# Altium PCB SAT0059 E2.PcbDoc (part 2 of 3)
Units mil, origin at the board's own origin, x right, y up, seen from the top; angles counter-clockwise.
Board outline 3960.27 x 3100.03 mil, 6 copper layers (Top Layer, GND, Power, Inner Routing, GND 2, Bottom Layer), stack 59.2 mil thick; 276 components, 209 nets, 812 pads, 621 vias.
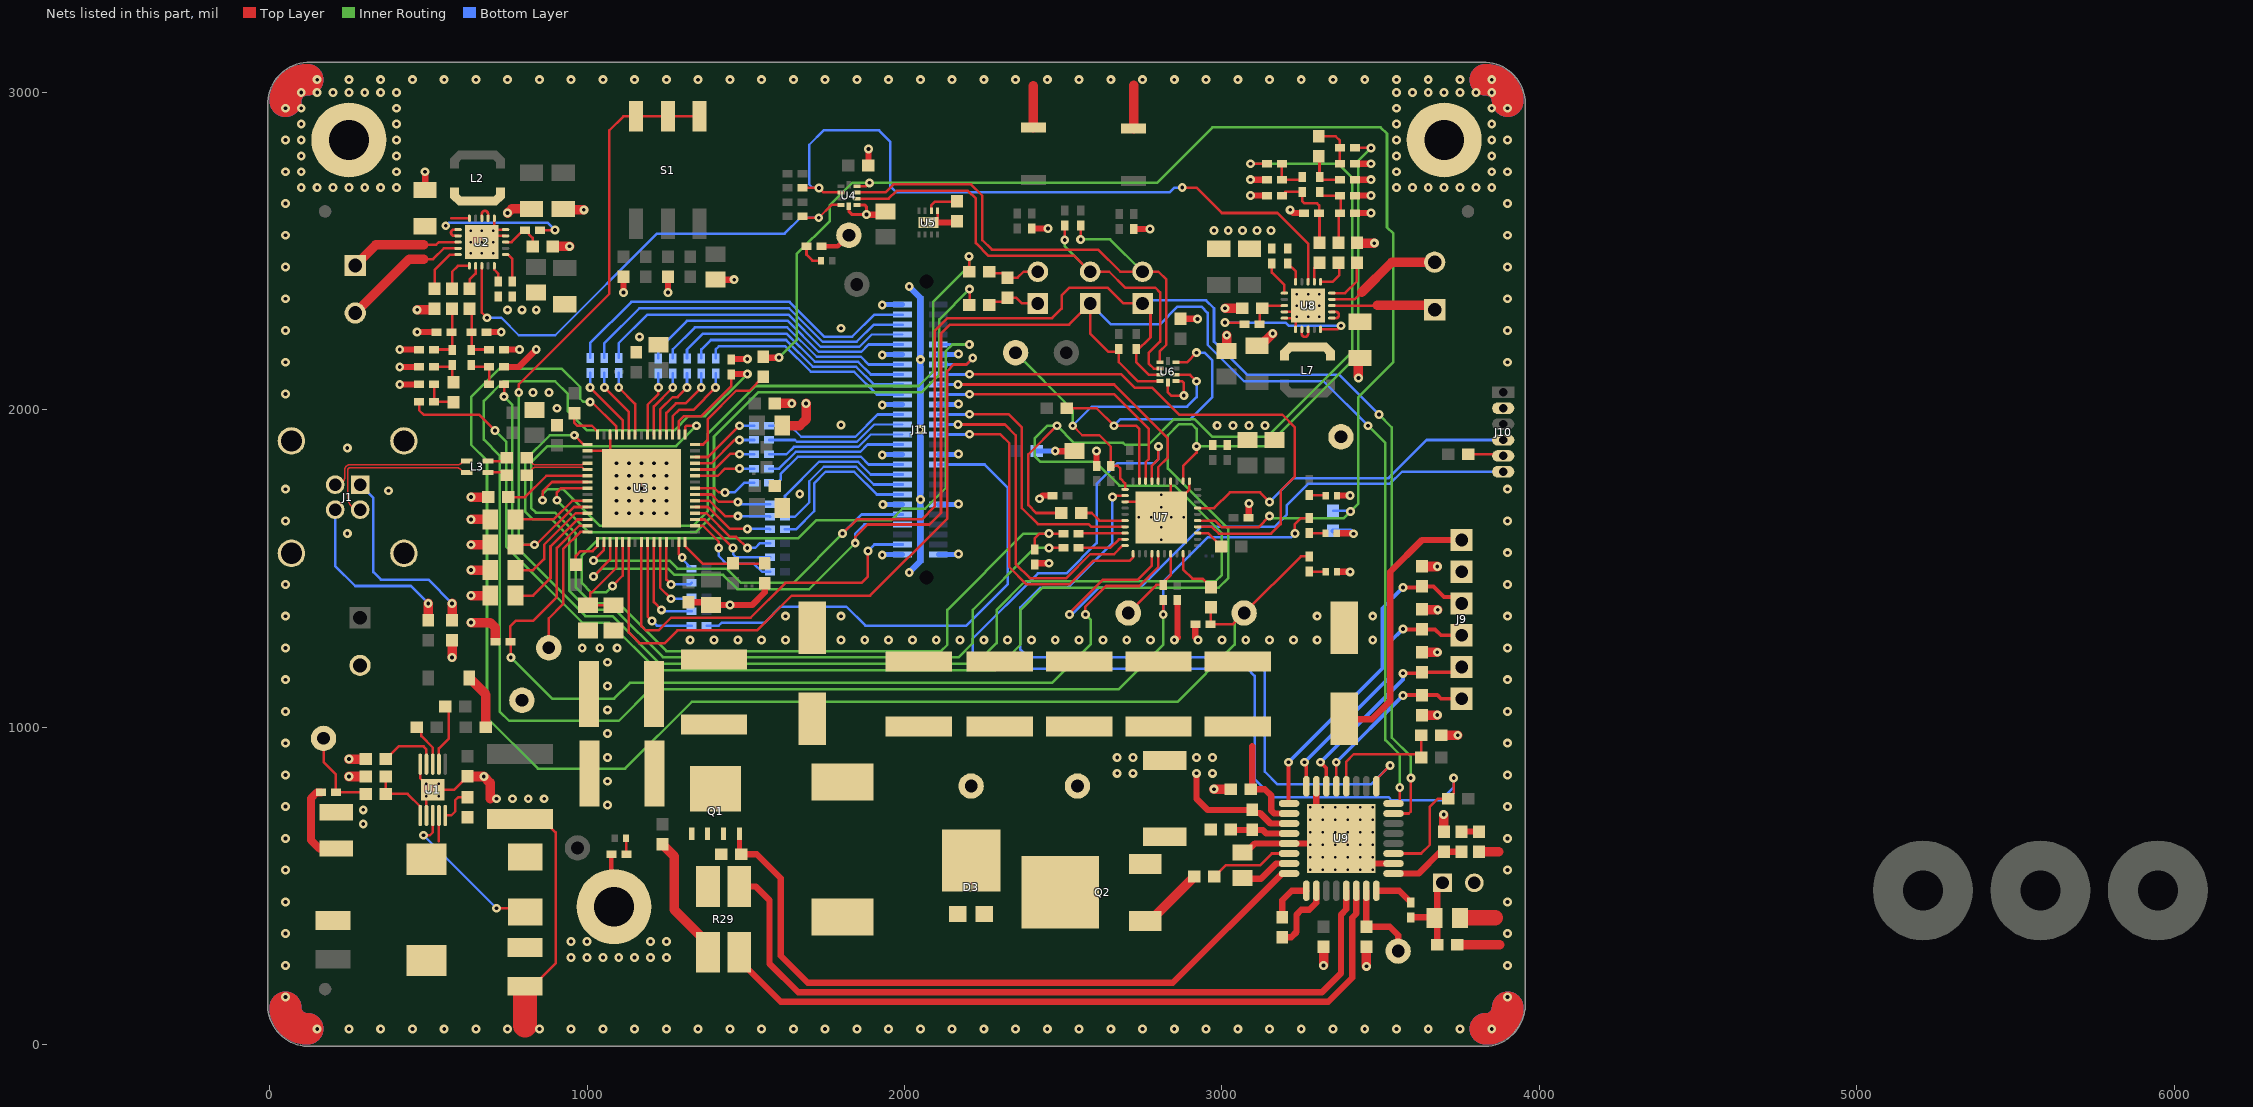
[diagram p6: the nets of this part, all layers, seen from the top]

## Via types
v1: diameter 28, hole 12, Top Layer to Bottom Layer, 528 vias
v2: diameter 19.68, hole 7.87, Top Layer to Bottom Layer, 44 vias
v3: diameter 23.62, hole 11.81, Top Layer to Bottom Layer, 25 vias
v4: diameter 19.68, hole 7.87, Top Layer to Bottom Layer, tented both sides, 20 vias
v5: diameter 18.75, hole 7.87, Top Layer to Bottom Layer, 4 vias

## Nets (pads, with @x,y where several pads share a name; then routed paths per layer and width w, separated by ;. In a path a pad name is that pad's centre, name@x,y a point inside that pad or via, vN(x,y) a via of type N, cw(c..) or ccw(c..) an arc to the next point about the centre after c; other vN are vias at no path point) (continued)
BLU7: J11.34 R99.2 | length 1605.9
  Bottom Layer w8: R99.2@1376.81,1320 1415,1320 1425,1330 1560,1330 1610,1380 1816.56,1380 1876.56,1320 2195,1320 2325.12,1450.12 2325.12,1754.88 2252.24,1827.76 J11.34@2106.1,1827.76
CMLOUTN: C48.1 U3.53 | length 2081
  Top Layer w8: v1(905,1715) 905,1740 918.01,1753.01 U3.53@1002.06,1753.01 ; C48.1@2203.5,2330 2205,2331.5 v1(2205,2380)
  Inner Routing w8: v1(905,1715) 1005,1615 1343.28,1615 1400,1671.72 1400,1916.02 1538.98,2055 2053.28,2055 2110,2111.72 2110,2285 v1(2205,2380)
CMLOUTP: C47.1 U3.52 | length 2289.2
  Top Layer w8: v1(860,1715) 860,1742.99 889.7,1772.7 U3.52@1002.06,1772.7 ; C47.1@2203.5,2435 v1(2203.5,2483.5)
  Inner Routing w8: v1(860,1715) 860,1735 875,1750 925,1750 1040,1635 1335,1635 1380,1680 1380,1924.31 1530.69,2075 2045,2075 2090,2120 2090,2339.98 2203.5,2453.49 v1(2203.5,2483.5)
DEN: J11.14 U3.6 | length 2143.9
  Top Layer w8: U3.6@1131.98,1583.72 1131.98,1298.02 1165,1265 1245,1265 1285,1305 1535,1305 1645,1415 1892,1415 2135,1658 2135,2122.72 2155,2142.72 2194.76,2142.72 v1(2215,2162.96)
  Bottom Layer w8: J11.14@2106.1,2142.72 2194.76,2142.72 v1(2215,2162.96)
DRV_FILTER_EN: R7.2 R71.2 U7.2 | length 5462
  Top Layer w8: R7.2@471.38,2025 471.38,1998.62 485,1985 660,1985 v1(710,1935) ; U7.2@2877.9,1775.17 2877.9,1822.9 2920,1865 v1(2920,1885) ; R71.2@3418.62,2825 v1(3470,2825)
  Inner Routing w8: v1(710,1935) 745,1900 745,1570 985,1330 1070,1330 1220,1180 2285,1180 2365,1260 2365,1370 2435,1440 2990,1440 3020,1470 3020,1625 2830,1815 2830,1920 2865,1955 2905,1955 2920,1940 v1(2920,1885) 3140.5,1885 3430,2174.5 3430,2785 v1(3470,2825)
DRV_PWM: R18.1 R44.1 R63.1 | length 6506.4
  Top Layer w8: v1(738.62,2041.38) R18.1@738.62,2080 ; v1(2480,1950) 2390,1860 2390,1700 2415,1675 R44.1@2493.5,1675 ; v1(3090,2775) R63.1@3141.38,2775
  Inner Routing w8: v1(738.62,2041.38) 765,2015 765,1580 995,1350 1080,1350 1230,1200 2225,1200 2290,1265 2290,1370 2380,1460 2980,1460 3000,1480 3000,1611.16 2850,1761.16 2677.07,1761.16 2602.23,1836 2429,1836 2410,1855 2410,1910 2450,1950 v1(2480,1950) 2534,1896 2689,1896 2695,1890 2768.23,1890 2849.23,1971 2911.63,1971 2912.63,1970 2915,1970 2970,1915 3142.27,1915 3410,2182.73 3410,2731.65 3366.65,2775 v1(3090,2775)
FB: C49.1 C51.1 C54.1 C57.1 C62.1 C74.1 D3.3 J9.1 U9.26 VBOOST.1 | length 1123.3
  Top Layer w20: 3095,940 3095,808.5 C62.1@3091.5,805 3135,805 3155,785 3155,738 3164.57,728.43 U9.26@3211.57,728.43 ; C74.1@3420,1025 3472.06,1025 3530,1082.94 3530,1490 3630,1590 J9.1@3755,1590
GND: C1.2 C2.2 C3.2 C4.2 C5.2 C8.2 C10.2 C11.2 C12.2 C14.2 C15.2 C16.2 C17.2 C18.2 C19.2 C22.2 C23.2 C24.2 C25.2 C26.2 C27.2 C28.2 C29.2 C30.2 C31.2 C32.2 C33.2 C34.2 C35.2 C36.2 C37.2 C38.2 C39.2 C40.2 C41.2 C42.2 C43.2 C44.2 C45.2 C46.2 C49.2 C50.2 C51.2 C52.2 C53.2 C54.2 C55.2 C56.2 C57.2 C58.2 C59.2 C60.2 C61.2 C62.2 C63.2 C64.2 C65.2 C66.2 C67.1 C68.2 C69.2 C70.2 C71.2 C73.2 C74.2 C76.1 C78.2 C79.2 C80.2 C81.2 C82.2 C83.2 C84.2 C85.2 C86.2 D4.2 D5.2 D6.2 J1.5 J1.6 J1.7 J1.8 J3.2 J8.2 J9.2 J10.2 J11.1 J11.11 J11.12 J11.21 J11.22 J11.31 J11.32 J11.41 J11.42 J11.51 J11.52 J11.53 J11.54 J11.55 J11.56 pad.0 R3.1 R6.1 R9.1 R10.1 R12.1 R16.1 R19.1 R20.1 R22.1 R25.1 R27.1 R30.1 R33.1 R35.1 R42.1 R43.1 R52.1 R54.1 R56.1 R60.1 R61.1 R65.1 R72.1 R73.1 R74.1 R75.1 R77.2 R79.2 R107.1 R108.1 R111.2 R113.2 RESET.2 RT1.1 TP11.1 TP12.1 TP13.1 U1.5 U1.7 U1.11 U2.4 U2.5 U2.6 U2.21 U3.43 U3.47 U3.61 U4.5 U4.6 U5.5 U5.9 U6.5 U6.6 U7.1 U7.4 U7.13 U7.41 U8.4 U8.5 U8.6 U8.21 U9.10 U9.23 U9.27 U9.29 U9.33 USER.2 | length 10442
  Top Layer w8: U1.5@474.63,883.71 474.63,839.37 511,803 U1.11@514,803 581.48,803 624,845.52 C8.2@624,846.5 ; U1.7@494.32,722.29 v5(494.31,783.32) ; U2.21@688.18,2548.04 U2.4@743.3,2548.04 ; U2.6@707.87,2603.16 707.87,2567.73 U2.5@743.3,2567.73 ; R20.1@805,183.98 828.98,183.98 901,256 901,669 C18.2@859.36,710.64 ; U3.47@1002.06,1871.12 U3.61@1053.24,1871.12 ; U3.61@1072.93,1851.44 U3.43@1072.93,1922.3 ; U5.9@2104.53,2595.47 U5.5@2104.53,2627.4 ; U7.13@2694.83,1710.21 U7.41@2759.79,1710.21 ; U7.41@2809,1661 U7.41@2838.53,1690.53 ; U6.5@2830,2086.14 2830,2055 2840,2045 v1(2880,2045) 2880,2085 2874.53,2090.47 U6.6@2855.2,2090.47 ; U7.4@2838.53,1775.17 U7.41@2838.53,1690.53 ; U7.1@2897.58,1775.17 2897.58,1749.58 U7.41@2838.53,1690.53 ; U8.5@3196.56,2288.9 3231.99,2288.9 U8.6@3231.99,2253.47 ; U8.4@3196.56,2308.59 U8.21@3251.68,2308.59
  Top Layer w10: U4.5@1825,2641.14 1825,2625 1835,2615 v1(1880,2615) 1880,2640 1874.53,2645.47 U4.6@1850.2,2645.47
  Top Layer w15: pad.0@1076.38,443.62 R107.1@1076.38,600 ; R108.1@1738.62,2515 1790,2515 TP13.1@1825,2550
  Top Layer w20: v1(410,2080) R6.1@471.38,2080 ; v1(410,2135) C5.2@471.38,2135 ; v1(410,2190) C4.2@471.38,2190 ; v1(465,2245) R10.1@526.38,2245 ; C3.2@490,2692.09 v1(490,2750) ; R16.1@683.62,2245 v1(730,2245) ; C17.2@740.59,2135 785,2135 v1(840,2190) ; C16.2@740.59,2190 v1(786.97,2190) ; v1(1115,2370) R25.1@1115,2415.57 ; v1(1255,2370) R27.1@1255,2415.57 ; C36.2@1320,1393.5 1381.5,1393.5 C37.2@1390,1385 v1(1450,1385) 1520,1385 1560,1425 R35.1@1560,1450.55 ; R30.1@1417.93,2410 v1(1463.5,2410) ; R33.1@1455,2158.62 1456.38,2160 v1(1505,2160) ; v1(1880,2615) 1930,2615 C44.2@1940,2625 ; C43.2@1886.5,2770 v1(1886.5,2821.5) ; U5.9@2075,2590 v2(2090.75,2590) ; U5.9@2104.53,2590 2161.5,2590 C46.2@2165,2593.5 ; C50.2@2401,2571.02 v1(2452.38,2571.02) ; R42.1@2410,1513.19 2413.62,1516.81 v1(2455,1516.81) ; v1(2425,1720) 2435,1730 R43.1@2466.38,1730 ; v1(2475,1870) C52.2@2535,1870 ; C53.2@2605,1823.62 v1(2605,1870) ; C55.2@2722,2569.38 v1(2773.38,2569.38) ; R54.1@2860,1401.38 2860,1285 2861.38,1283.62 ; C56.2@2870,2286.5 v1(2923.5,2286.5) ; R56.1@2916.38,1325 2916.38,1283.62 v1(2925,1275) ; v1(2920,855) 2920,775 2955.39,739.61 C67.1@3095.63,739.61 ; C63.2@3065,615 3085,615 3103.94,633.94 U9.29@3211.57,633.94 U9.33@3360.2,633.94 ; R60.1@3083.62,1660 3085,1661.38 v1(3085,1705) ; v1(3090,2675) C69.2@3141.38,2675 ; v1(3090,2725) C68.2@3141.38,2725 ; C67.1@3105.24,730 3120,730 3153.07,696.93 U9.27@3211.57,696.93 ; v1(3215,2630) 3225,2620 R65.1@3258.74,2620 ; U9.33@3297.2,728.43 U9.23@3297.2,814.06 ; D4.2@3361.48,1611.24 3412.52,1611.24 v1(3414.02,1609.74) ; D6.2@3363.02,1490 v1@3403.76,1490 ; D5.2@3363.02,1730 3403.76,1730 v1(3404.02,1729.74) ; R73.1@3418.62,2620 v1(3470,2620) ; C79.2@3418.62,2675 v1(3470,2675) ; C78.2@3418.62,2725 v1(3470,2725) ; R72.1@3418.62,2775 v1(3470,2775) ; U9.33@3454.69,570.94 U9.10@3540.31,570.94
  Top Layer w30: v1(250,845) R3.1@303.5,845 ; v1(250,900) C2.2@303.5,900 ; v1(465,2315) 516.5,2315 R9.1@520,2318.5 ; v1(575,1220) R12.1@575,1273.5 ; C8.2@624,846.5 625.5,845 v1(675,845) 695,825 695,775 ; v1(635,1330) 695,1330 711.38,1313.62 R19.1@711.38,1280 ; v1(635,1415) C15.2@695,1415 ; v1(635,1495) C12.2@695,1495 ; v1(635,1575) C14.2@695,1575 ; v1(635,1655) C11.2@695,1655 ; v1(635,1725) C10.2@685.57,1725 ; v1(750,2620) 762.91,2632.91 C23.2@825,2632.91 ; R22.1@891.5,2515 v1(945,2515) ; C26.2@925,2632.91 927.91,2630 v1(990,2630) ; C38.2@1591.5,2020 v1(1645,2020) ; C40.2@1615,1950 1670,1950 1690,1970 v1(1690,2020) ; RESET.2@2406,2888.69 2406,3021 ; USER.2@2722,2885.68 2722,3022 ; v1(2975,805) C62.2@3028.5,805 ; v1(3010,2320) R61.1@3060.57,2320 ; C60.2@3015,2180 v1(3015,2235) ; C66.2@3110,2192.09 C66.2@3122.09,2192.09 ; C66.2@3122.09,2202.09 v1(3160,2240) ; v1(3320,250) C76.1@3320,308.5 ; R74.1@3425,2526.5 3426.5,2525 v1(3480,2525) ; v1@3430,2105 C80.2@3430,2162.91 ; v1(3455,247.07) R75.1@3455,305.57 ; C84.2@3628.5,1040 C84.2@3630,1038.5 v1(3678.5,1038.5) ; C83.2@3628.5,1237.99 C83.2@3630,1236.5 v1(3678.5,1236.5) ; C81.2@3628.5,1507.99 C81.2@3630,1506.5 v1(3678.5,1506.5) ; C82.2@3630,1371.5 3631.5,1370 v1(3680,1370) ; R77.2@3692.93,976.5 3694.43,975 v1(3742.93,975) ; v1(3698.5,725) 3698.5,676.5 C85.2@3700,675 ; R79.2@3741.5,315 3875,315 ; C86.2@3810,608.5 3871.5,608.5
  Top Layer w50: RT1.1@3750,400 3860,400
  Top Layer w75: 805,60 R20.1@805,165
  Top Layer w100: 50,118 ccw(c118,118.01) 120.22,50.05 ; 50,2972 cw(c118,2971.99) 120.22,3039.95 ; 3829.78,3039.95 cw(c3832,2971.99) 3900,2972 ; 3830,50 ccw(c3832.22,117.96) 3900.22,117.95
  Bottom Layer w15: v1@1931.22,1544.3 J11.51@1993.9,1544.3 ; v1@1931.22,1859.26 J11.31@1993.9,1859.26 ; v1@1931.22,2016.74 J11.21@1993.9,2016.74 ; v1@1931.22,2174.22 J11.11@1993.9,2174.22 ; v1@1931.22,2331.7 J11.1@1993.9,2331.7 ; v1(1931.78,1701.78) J11.41@1993.9,1701.78 ; J11.52@2106.1,1544.3 v1@2168.78,1544.3 ; J11.42@2106.1,1701.78 v1@2168.78,1701.78 ; J11.32@2106.1,1859.26 v1@2168.78,1859.26 ; J11.22@2106.1,2016.74 v1@2168.78,2016.74 ; J11.12@2106.1,2174.22 v1@2168.78,2174.22 ; R111.2@2416.5,1870 v1(2475,1870) ; R113.2@3350,1618.5 3405.26,1618.5 v1(3414.02,1609.74)
  Bottom Layer w20: v1(2015,1488) 2050,1523 J11.56@2050,1607.29 v1(2050,1718) J11.55@2050,1827.76 J11.54@2050,2048.24 v1(2050,2158) J11.53@2050,2268.71 2050,2353 v1(2015,2388)
  Bottom Layer w100: 50,118 ccw(c118,118.01) 120.22,50.05 ; 50,2972 cw(c118,2971.99) 120.22,3039.95 ; 3829.78,3039.95 cw(c3832,2971.99) 3900,2972 ; 3830,50 ccw(c3832.22,117.96) 3900.22,117.95
  other v1: 150,50 250,50 350,50 450,50 550,50 650,50 750,50 850,50 950,50 1050,50 1150,50 1250,50 1350,50 1450,50 1550,50 1650,50 1750,50 1850,50 1950,50 2050,50 2150,50 2250,50 2350,50 2450,50 2550,50 2650,50 2750,50 2850,50 2950,50 3050,50 3150,50 3250,50 3350,50 3450,50 3550,50 3650,50 3750,50 3850,50 50,150 3900,150 50,250 3900,250 950,275 1000,275 1050,275 1100,275 1150,275 1200,275 1250,275 950,325 1000,325 1200,325 1250,325 50,350 3900,350 50,450 3900,450 50,550 3900,550 50,650 3900,650 295,695 295,740 50,750 3900,750 1065,755 715,775 765,775 815,775 865,775 1065,830 50,850 3900,850 2670,855 2720,855 2970,855 1065,905 2670,905 2720,905 2920,905 2970,905 50,950 3900,950 1065,980 50,1050 3900,1050 1065,1055 1065,1130 50,1150 3900,1150 1065,1205 50,1250 985,1250 1040,1250 1095,1250 3900,1250 1325,1275 1400,1275 1475,1275 1550,1275 1625,1275 1800,1275 1875,1275 1950,1275 2025,1275 2100,1275 2175,1275 2250,1275 2325,1275 2400,1275 2475,1275 2550,1275 2625,1275 2700,1275 2775,1275 2850,1275 3000,1275 3075,1275 3150,1275 3225,1275 3300,1275 3475,1275 50,1350 1625,1350 1800,1350 3300,1350 3475,1350 3900,1350 50,1450 3900,1450 3404.02,1489.74 1930,1543.08 2170,1545.52 3900,1550 245,1610 50,1650 3900,1650 2170,1703 1670,1735 375,1745 50,1750 3900,1750 1930,1858.04 2170,1860.48 245,1880 2049.88,1937.48 2985,1951 3035,1951 3085,1951 3136,1951 1800,1952.12 905,2005 1930,2015.52 2170,2017.96 50,2050 830,2055 880,2055 3430,2100 50,2150 3900,2150 1930,2173 2170,2175.44 1165,2230 50,2250 3900,2250 1800,2257.12 750,2315 795,2315 840,2315 1930,2330.48 50,2350 3900,2350 50,2450 3900,2450 50,2550 3900,2550 2975,2565 3020,2565 3065,2565 3110,2565 3155,2565 50,2650 3900,2650 100,2700 150,2700 200,2700 250,2700 300,2700 350,2700 400,2700 3550,2700 3600,2700 3650,2700 3700,2700 3750,2700 3800,2700 3850,2700 50,2750 100,2750 400,2750 3550,2750 3850,2750 3900,2750 100,2800 400,2800 3550,2800 3850,2800 50,2850 100,2850 400,2850 3550,2850 3850,2850 3900,2850 100,2900 400,2900 3550,2900 3850,2900 50,2950 100,2950 400,2950 3550,2950 3850,2950 3900,2950 100,3000 150,3000 200,3000 250,3000 300,3000 350,3000 400,3000 3550,3000 3600,3000 3650,3000 3700,3000 3750,3000 3800,3000 3850,3000 150,3040 250,3040 350,3040 450,3040 550,3040 650,3040 750,3040 850,3040 950,3040 1050,3040 1150,3040 1250,3040 1350,3040 1450,3040 1550,3040 1650,3040 1750,3040 1850,3040 1950,3040 2050,3040 2150,3040 2250,3040 2350,3040 2450,3040 2550,3040 2650,3040 2750,3040 2850,3040 2950,3040 3050,3040 3150,3040 3250,3040 3350,3040 3450,3040 3550,3040 3650,3040 3750,3040 3850,3040
  other v2: 3316.89,590.63 3356.26,590.63 3395.63,590.63 3435,590.63 3316.89,630 3356.26,630 3395.63,630 3435,630 3316.89,669.37 3356.26,669.37 3395.63,669.37 3435,669.37 3316.89,708.74 3356.26,708.74 3395.63,708.74 3435,708.74 2809,1590.13 2809,1629.5 2738.13,1661 2777.5,1661 2840.5,1661 2879.87,1661 2809,1692.5 2809,1731.87 3235.93,2292.84 3271.36,2292.84 3306.79,2292.84 3235.93,2328.27 3271.36,2328.27 3306.79,2328.27 3235.93,2363.71 3271.36,2363.71 3306.79,2363.71 633.07,2492.92 668.5,2492.92 703.93,2492.92 633.07,2528.35 668.5,2528.35 703.93,2528.35 633.07,2563.79 668.5,2563.79 703.93,2563.79 2059.25,2590
  other v3: 1092.61,1674.27 1131.98,1674.27 1171.35,1674.27 1210.72,1674.27 1250.1,1674.27 1092.61,1713.64 1131.98,1713.64 1171.35,1713.64 1210.72,1713.64 1250.1,1713.64 1092.61,1753.01 1131.98,1753.01 1171.35,1753.01 1210.72,1753.01 1250.1,1753.01 1092.61,1792.38 1131.98,1792.38 1171.35,1792.38 1210.72,1792.38 1250.1,1792.38 1092.61,1831.75 1131.98,1831.75 1171.35,1831.75 1210.72,1831.75 1250.1,1831.75
  other v4: 3277.52,551.26 3316.89,551.26 3356.26,551.26 3395.63,551.26 3435,551.26 3474.37,551.26 3277.52,590.63 3474.37,590.63 3277.52,630 3474.37,630 3277.52,669.37 3474.37,669.37 3277.52,708.74 3474.37,708.74 3277.52,748.11 3316.89,748.11 3356.26,748.11 3395.63,748.11 3435,748.11 3474.37,748.11
  other v5: 533.68,783.32 494.31,822.68 533.68,822.68
GPIO_REG6: R23.2 U3.45 | length 123.6
  Top Layer w8: R23.2@960,1988.5 960,1958.98 968.98,1950 1015,1950 1033.56,1931.44 U3.45@1033.56,1922.3
GPIO_REG7: R34.2 U3.30 | length 340.5
  Top Layer w8: U3.30@1340.65,1890.81 1365.81,1890.81 1380,1905 1380,1970 1470,2060 1511.5,2060 R34.2@1555,2103.5
GPIO_REG8: R24.2 U3.1 | length 122.7
  Top Layer w8: R24.2@965,1511.5 965,1539.98 980.02,1555 1017.63,1555 1033.56,1570.93 U3.1@1033.56,1583.72
GRN0: J11.23 R89.2 | length 463.8
  Bottom Layer w8: R89.2@1573.62,1950 1640,1950 1674.88,1915.12 1845.12,1915.12 1915.24,1985.24 J11.23@1993.9,1985.24
GRN1: J11.25 R90.2 | length 445.5
  Bottom Layer w7: 1849.88,1899.37 1850.58,1899.37 1904.96,1953.75 J11.25@1993.9,1953.75
  Bottom Layer w8: R90.2@1573.62,1905 1655,1905 1660.63,1899.37 1849.88,1899.37 1850.12,1899.62
GRN2: J11.27 R91.2 | length 446.1
  Bottom Layer w7: 1854.63,1883.62 1855.34,1883.62 1893.97,1922.25 J11.27@1993.9,1922.25
  Bottom Layer w8: R91.2@1573.62,1860 1628.08,1860 1651.45,1883.37 1669.75,1883.37 1670,1883.62 1854.63,1883.62
GRN3: J11.29 R92.2 | length 451.7
  Bottom Layer w8: R92.2@1573.62,1815 1605,1815 1657.87,1867.87 1860.81,1867.87 1883.69,1890.76 J11.29@1993.9,1890.76
GRN4: J11.33 R93.2 | length 475
  Bottom Layer w8: R93.2@1573.62,1770 1600,1770 1610,1780 1610,1798.08 1664.05,1852.13 1862.87,1852.13 1887.24,1827.76 J11.33@1993.9,1827.76
GRN5: J11.35 R83.2 | length 456.9
  Bottom Layer w8: R83.2@1623.62,1703.21 1623.62,1728.62 1731.38,1836.38 1853.62,1836.38 1893.73,1796.27 J11.35@1993.9,1796.27
GRN6: J11.37 R84.2 | length 497.7
  Bottom Layer w8: R84.2@1623.62,1663.21 1655,1663.21 1700,1708.21 1700,1775 1745.63,1820.63 1847.45,1820.63 1903.31,1764.77 J11.37@1993.9,1764.77
GRN7: J11.39 R85.2 | length 526.8
  Bottom Layer w8: R85.2@1623.62,1623.21 1658.21,1623.21 1715.5,1680.5 1715.5,1768.58 1751.8,1804.88 1841.28,1804.88 1912.88,1733.28 J11.39@1993.9,1733.28
HD: J11.49 U3.8 | length 1252.6
  Top Layer w8: U3.8@1171.35,1583.72 1171.35,1318.65 1185,1305 1225,1305 1265,1345 1515,1345 1625,1455 1865,1455 1885,1475 v1(1885,1555.56)
  Bottom Layer w8: v1(1885,1555.56) 1905.24,1575.8 J11.49@1993.9,1575.8
I2C_DRV_SW: R34.1 R113.1 U4.9 U7.35 | length 4332.4
  Top Layer w8: U4.9@1850.2,2704.53 1879.53,2704.53 v1(1890,2715) ; U7.35@2923.17,1651.16 2978.84,1651.16 3000,1630 3115,1630 v1(3150,1665)
  Top Layer w20: R34.1@1555,2163.05 1556.38,2164.43 v1(1605,2164.43)
  Inner Routing w8: v1(1605,2164.43) 1660.57,2220 1660.57,2490.57 1765,2595 1765,2645 1835,2715 v1(1890,2715) 2795,2715 2970,2890 3500,2890 3520,2870 3520,2575 3540,2555 3540,2150 3430,2040 3430,1740.53 ; v1(3150,1665) 3156,1659 3384,1659 v1(3405,1680) 3430,1705 3430,1718.96 ; 3430.02,1718.98 3430.02,1740.51
  Bottom Layer w8: R113.1@3350,1681.5 3403.5,1681.5 v1(3405,1680)
I2C_UC_SW: R114.2 U6.9 U7.9 | length 1020.4
  Top Layer w8: R114.2@2511.5,2005 2605,2005 v1(2660,1950) 2730,1950 2740.1,1939.9 U7.9@2740.1,1775.17 ; U6.9@2855.2,2149.53 2889.53,2149.53 v1(2920,2180)
  Bottom Layer w8: v1(2660,1950) 2681,1971 2901,1971 2970,2040 2970,2155 2945,2180 v1(2920,2180)
IF: R77.1 R78.2 U9.20 | length 389.1
  Top Layer w8: U9.20@3391.69,814.06 3391.69,891.69 3415,915 R78.2@3623.5,915 ; R78.2@3628.5,905 R77.1@3628.5,975
ISET: ISET.1 R75.2 U9.7 | length 274.9
  Top Layer w20: U9.7@3454.69,485.31 3454.69,371.81 R75.2@3455,371.5 3528.5,371.5 3555,345 ISET.1@3555,295
LCD_GPIO_1: J11.16 U7.34 | length 1799.1
  Top Layer w8: v1(2205,2111.94) 2683.06,2111.94 2725,2070 2780,2070 2865,1985 3190,1985 3230,1945 3230,1790 3185,1745 3185,1640 3155,1610 2990,1610 2968.53,1631.47 U7.34@2923.17,1631.47
  Bottom Layer w8: J11.16@2106.1,2111.23 v1@2204.29,2111.23
LCD_GPIO_2: J11.18 U7.6 | length 941.8
  Top Layer w8: v1(2168.78,2079.73) 2660.27,2079.73 2830,1910 2830,1850 2799.16,1819.16 U7.6@2799.16,1775.17
  Bottom Layer w8: J11.18@2106.1,2079.73 v1(2168.78,2079.73)
LCD_GPIO_3: J11.20 U7.8 | length 877.4
  Top Layer w8: v1(2205,2048.94) 2661.06,2048.94 2770,1940 2770,1845 2759.79,1834.79 U7.8@2759.79,1775.17
  Bottom Layer w8: J11.20@2106.1,2048.24 v1@2204.29,2048.24
LCD_GPIO_4: J11.24 U7.17 | length 884.9
  Top Layer w8: v1(2205,1985.95) 2329.05,1985.95 2370,1945 2370,1690 2420,1640 2580,1640 2588.53,1631.47 U7.17@2694.83,1631.47
  Bottom Layer w8: J11.24@2106.1,1985.24 v1@2205,1985.24
LCD_GPIO_5: J11.26 U7.20 | length 1068.8
  Top Layer w8: v1(2168.78,1953.75) 2316.25,1953.75 2350,1920 2350,1515 2395,1470 2510,1470 2585,1545 2660,1545 2687.42,1572.42 U7.20@2694.83,1572.42
  Bottom Layer w8: J11.26@2106.1,1953.75 v1(2168.78,1953.75)
LCD_GPIO_6: J11.28 U7.21 | length 1085.5
  Top Layer w8: v1(2205,1922.96) 2302.04,1922.96 2330,1895 2330,1505 2385,1450 2520,1450 2595,1525 2710,1525 2720.42,1535.42 U7.21@2720.42,1546.83
  Bottom Layer w8: J11.28@2106.1,1922.25 v1@2205,1922.25
LOCK: R33.2 R53.1 R67.2 U3.32 | length 5371.3
  Top Layer w8: U3.32@1289.47,1922.3 1289.47,1964.47 1305,1980 1360,1980 1455,2075 R33.2@1455,2111.38 ; v1(2815,1355) R53.1@2815,1401.38 ; v1(3230,1610) 3230,1640 3248.62,1658.62 R67.2@3275,1658.62
  Top Layer w20: R33.2@1455,2111.38 1456.38,2112.76 v1(1505,2112.76)
  Inner Routing w8: v1(1505,2112.76) 1372.24,1980 1320,1980 1275,1935 1000.02,1935 940,1995.02 940,2049.37 899.37,2090 736.81,2090 675,2028.19 675,1906.57 725,1856.57 725,1050 755,1020 1100,1020 1200,1120 2675.39,1120 2815,1259.61 v1(2815,1355)
  Bottom Layer w8: v1(2815,1355) 2815,1457.28 2956.72,1599 3219,1599 v1(3230,1610)
LOOP: R2.1 R4.2 TP2.1 | length 283
  Top Layer w8: TP2.1@170,965 170,890 208.62,851.38 R2.1@208.62,795 298.5,795 R4.2@303.5,790
NCLK: J11.10 U3.5 | length 2202.1
  Top Layer w8: v1(1080,1445) 1112.3,1477.3 U3.5@1112.3,1583.72
  Inner Routing w8: v1(1080,1445) 1060,1425 1013.2,1425 983.7,1454.5 983.7,1540.5 1038.2,1595 1665,1595 1722,1652 1957,1652 1993.3,1688.3 2065,1688.3 2130,1753.3 2130,2185 2150.72,2205.72 v1(2204.28,2205.72)
  Bottom Layer w8: J11.10@2106.1,2205.72 v1(2204.28,2205.72)
NetC1_1: C1.1 L1.2 R1.1 R2.2 | length 208.5
  Top Layer w25: C1.1@156.87,617.91 130,644.78 130,776 149,795 R2.2@161.38,795
NetC2_1: C2.1 U1.4 | length 195.2
  Top Layer w8: C2.1@366.5,900 406.5,940 485,940 494.32,930.68 U1.4@494.32,883.71
NetC3_1: C3.1 R21.2 U2.10 U2.11 U2.12 | length 533.4
  Top Layer w8: C3.1@477.09,2577.91 C3.1@490,2577.91 ; 573.16,2603.16 U2.10@629.13,2603.16 ; U2.12@595.17,2548.04 580.02,2548.04 cw(c581.54,2557.88) 580.02,2567.72 U2.11@595.17,2567.72 ; R21.2@851.12,2566 v1(899,2566)
  Bottom Layer w8: v1(555,2580) 565,2590 875,2590 v1(899,2566)
NetC4_1: C4.1 C6.2 R10.2 R14.2 | length 188
  Top Layer w8: C4.1@518.62,2190 573.62,2190 R14.2@575,2188.62 575,2243.62 R10.2@573.62,2245 575,2246.38 C6.2@575,2318.5
NetC5_1: C5.1 R13.1 R14.1 | length 126
  Top Layer w8: C5.1@518.62,2135 568.62,2135 R14.1@575,2141.38 575,2081.5 R13.1@580,2076.5
NetC6_1: C6.1 U2.16 | length 115.3
  Top Layer w8: C6.1@575,2381.5 575,2435 593.55,2453.55 U2.16@629.13,2453.55
NetC7_1: C7.1 D2.1 L1.1 U1.9 | length 81
  Top Layer w8: 533.69,641.31 U1.9@533.69,722.29
NetC7_2: C7.2 U1.10 | length 115
  Top Layer w8: U1.10@553.37,722.29 572.29,722.29 585,735 585,770.27 594.23,779.5 C7.2@624,779.5
NetC9_1: C9.1 U2.17 | length 79.8
  Top Layer w8: C9.1@630,2381.5 630,2410 648.82,2428.82 U2.17@648.82,2453.55
NetC9_2: C9.2 C16.1 R16.2 R17.2 | length 188.1
  Top Layer w8: C9.2@630,2318.5 636.38,2312.13 R16.2@636.38,2245 R17.2@636.38,2190 ; R17.2@635,2188.62 R17.2@636.38,2190 ; C16.1@691.38,2190 R17.2@636.38,2190
NetC10_1: C10.1 U3.51 | length 278.5
  Top Layer w8: C10.1@751.5,1725 805,1725 872.38,1792.38 U3.51@1002.06,1792.38
NetC11_1: C11.1 U3.55 | length 251.4
  Top Layer w8: C11.1@775,1655 895,1655 953.64,1713.64 U3.55@1002.06,1713.64
NetC12_1: C12.1 U3.57 | length 324.4
  Top Layer w8: C12.1@778.29,1495 830,1495 865,1530 865,1575 964.27,1674.27 U3.57@1002.06,1674.27
NetC14_1: C14.1 S1.1 S1.2 S1.3 U3.56 | length 2043.9
  Top Layer w8: C14.1@778.29,1575 825,1575 v1@835,1585 ; v1(785,2055) 785,2080 1070,2365 1070,2880 1114.49,2924.49 S1.3@1155,2924.49 S1.2@1255,2924.49 S1.1@1355,2924.49 ; v1(835,1575) 840,1575 958.96,1693.96 U3.56@1002.06,1693.96
  Inner Routing w8: v1(785,2055) 785,1591.64 801.64,1575 v1(835,1575)
NetC15_1: C15.1 U3.58 | length 381.6
  Top Layer w8: C15.1@778.29,1415 830,1415 885,1470 885,1570 969.59,1654.59 U3.58@1002.06,1654.59
NetC17_1: C17.1 R17.1 R18.2 | length 114
  Top Layer w8: R17.1@635,2141.38 641.38,2135 C17.1@691.38,2135 R18.2@691.38,2080
NetC19_1: C19.1 U2.20 | length 55
  Top Layer w8: U2.20@707.87,2453.55 707.87,2441.34 720,2429.21 C19.1@720,2403.62
NetC20_1: C20.1 U3.49 | length 169.5
  Top Layer w5: C20.1@826.51,1835.97 ccw(c835,1835.97) 835,1827.49 984.5,1827.49 ccw(c984.5,1831.75) U3.49@988.77,1831.75
NetC20_2: C20.2 L3.3 | length 62.3
  Top Layer w8: L3.3@688.46,1838.72 736.22,1838.72 C20.2@746.5,1849
NetC21_1: C21.1 U3.50 | length 195.7
  Top Layer w5: C21.1@809.5,1794 cw(c825.5,1794) C21.1@825.5,1810 ; C21.1@826.51,1810 cw(c835,1810) 835,1818.49 ; 833.98,1818.49 984.51,1818.49 cw(c984.51,1814.22) U3.50@988.78,1814.22
NetC21_2: C21.2 L3.2 | length 61.9
  Top Layer w8: L3.2@688.46,1803.28 737.22,1803.28 C21.2@746.5,1794
NetC22_1: C22.1 U2.1 | length 98.9
  Top Layer w8: U2.1@743.3,2488.98 751.02,2488.98 765,2475 C22.1@765,2403.62
NetC29_1: C29.1 C32.1 U3.4 | length 313.8
  Top Layer w8: C29.1@1003,1384.5 C32.1@1083,1384.5 ; 1010,1425 1010,1407.5 C29.1@1028,1389.5 ; 1015,1425 1092.61,1502.61 U3.4@1092.61,1583.72
NetC30_1: C30.1 C31.1 C35.1 C42.1 C45.1 L6.1 Q1.5
NetC46_1: C46.1 U5.6 | length 102.4
  Top Layer w8: U5.6@2084.84,2627.4 2084.84,2644.84 2095,2655 2163.5,2655 C46.1@2165,2656.5
NetC47_2: C47.2 J4.2 R40.2 | length 166.8
  Top Layer w8: C47.2@2266.5,2430 2311.5,2430 R40.2@2325,2416.5 2356.5,2416.5 2375,2435 J4.2@2420,2435
NetC48_2: C48.2 J4.1 R40.1 | length 168.8
  Top Layer w8: C48.2@2266.5,2335 2271.5,2340 2311.5,2340 R40.1@2325,2353.5 2351.5,2353.5 2370,2335 J4.1@2420,2335
NetC63_1: C63.1 U9.31 | length 171.4
  Top Layer w20: C63.1@3060,523.11 3123.11,523.11 3170.94,570.94 U9.31@3211.57,570.94
NetC67_2: C67.2 R57.1 U9.28 | length 189.7
  Top Layer w20: R57.1@3027.13,678.11 3028.62,676.61 C67.2@3095.63,676.61 3128.39,676.61 3139.57,665.43 U9.28@3211.57,665.43
NetC68_1: C68.1 R63.2 R64.1 | length 117.3
  Top Layer w8: R63.2@3188.62,2775 C68.1@3188.62,2725 3243.74,2725 R64.1@3252.36,2733.62
NetC69_1: C69.1 C75.2 R64.2 R65.2 | length 274.5
  Top Layer w8: C69.1@3188.62,2675 3200,2686.38 R64.2@3252.36,2686.38 3252.36,2657.64 3260,2650 3300,2650 3305.98,2644.02 R65.2@3305.98,2620 3307.36,2618.62 C75.2@3307.36,2526.5
NetC71_1: C71.1 U8.1 | length 110
  Top Layer w8: C71.1@3157.36,2461.38 3157.36,2432.64 3196.56,2393.44 U8.1@3196.56,2367.64
NetC72_1: C72.1 U9.2 | length 202.8
  Top Layer w20: 3210,338.5 3218.5,338.5 3235,355 3235,410 3250,425 3275.44,425 3297.2,446.76 U9.2@3297.2,485.31
NetC72_2: C72.2 U9.1 | length 141.8
  Top Layer w20: C72.2@3190,401.5 3190,455 3220.31,485.31 U9.1@3265.71,485.31
NetC73_1: C73.1 U8.20 | length 68.5
  Top Layer w8: C73.1@3207.36,2461.38 3231.99,2436.75 U8.20@3231.99,2403.08
NetC75_1: C75.1 U8.17 | length 67.2
  Top Layer w8: U8.17@3291.05,2403.08 3291.05,2447.19 C75.1@3307.36,2463.5
NetC77_1: C77.1 U8.16 | length 106.9
  Top Layer w8: U8.16@3310.73,2403.08 3348.08,2403.08 3370,2425 C77.1@3370,2463.5
NetC77_2: C77.2 C79.1 R70.2 R73.2 | length 226.5
  Top Layer w8: R70.2@3307.36,2686.38 3307.36,2675 C79.1@3371.38,2675 ; C77.2@3367.36,2526.5 3367.36,2618.62 3373.74,2625 C79.1@3373.74,2675
NetC78_1: C78.1 R69.1 R70.1 | length 133.4
  Top Layer w8: R69.1@3305,2798.5 3307.36,2796.14 R70.1@3307.36,2733.62 3315.98,2725 C78.1@3371.38,2725
NetC80_1: C80.1 R62.2 U8.10 U8.11 U8.12 | length 558.8
  Top Layer w8: v1(3010,2275) 3066.38,2275 R62.2@3071.38,2270 ; U8.10@3310.73,2254 3365.47,2254 ; U8.11@3344.69,2288.9 3359.84,2288.9 ccw(c3358.32,2298.75) 3359.84,2308.59 U8.12@3344.69,2308.59 ; C80.1@3430,2277.09 C80.1@3442.91,2277.09
  Bottom Layer w8: v1(3010,2275) 3200,2275 3210,2265 v1(3375,2265)
NetC81_1: C81.1 J9.3 U9.25 | length 1036.2
  Top Layer w8: C81.1@3626.5,1440 C81.1@3630,1443.5
  Top Layer w12: U9.25@3210,761.5 v1(3210,890) ; v1(3570,1440) C81.1@3626.5,1440 ; C81.1@3630,1443.5 3666.5,1443.5 3700,1410 3735,1410 J9.3@3755,1390
  Bottom Layer w12: v1(3210,890) 3505,1185 3505,1375 v1(3570,1440)
NetC82_1: C82.1 J9.4 U9.24 | length 820
  Top Layer w8: v1(3570,1310) v1@3571.5,1308.5
  Top Layer w12: v1(3260,890) 3265.71,884.29 U9.24@3265.71,814.06 ; v1@3571.5,1308.5 C82.1@3630,1308.5 3671.5,1308.5 3690,1290 J9.4@3755,1290
  Bottom Layer w12: v1(3260,890) 3530,1160 3530,1270 v1(3570,1310)
NetC83_1: C83.1 J9.5 U9.22 | length 664.7
  Top Layer w8: C83.1@3626.5,1170 C83.1@3630,1173.5 ; J9.5@3738.5,1173.5 J9.5@3755,1190
  Top Layer w12: v1(3310,890) 3328.7,871.3 U9.22@3328.7,814.06 ; v1(3570,1170) C83.1@3626.5,1170 ; C83.1@3630,1173.5 J9.5@3738.5,1173.5
  Bottom Layer w12: v1(3310,890) 3570,1150 v1(3570,1170)
NetC84_1: C84.1 J9.6 U9.21 | length 563.1
  Top Layer w8: U9.21@3360.2,814.06 v1@3360.2,889.8 ; v1(3570,1100) v1@3571.5,1101.5
  Top Layer w12: v1@3571.5,1101.5 C84.1@3630,1101.5 3678.5,1101.5 3690,1090 J9.6@3755,1090
  Bottom Layer w12: v1(3360,890) v1(3570,1100)
NetC85_1: C85.1 R82.2 U9.9 | length 249.1
  Top Layer w20: U9.9@3540.31,539.45 3619.45,539.45 3688.19,608.19 3755,608.19 R82.2@3760.94,608.19
NetC86_1: C86.1 R82.1 | length 55
  Top Layer w20: R82.1@3755,671.5 C86.1@3810,671.5
NetD1_1: D1.1 R15.2 | length 176.6
  Top Layer w30: D1.1@629.47,1155 681.5,1102.97 R15.2@681.5,1000
NetD2_2: D2.2 R20.2 U1.8 | length 506.3
  Top Layer w8: v1(485,660) 505,660 514,669 U1.8@514,722.29 ; v1(715,430) 792.99,430 D2.2@805,417.99
  Bottom Layer w8: v1(485,660) v1(715,430)
NetD3_1: D3.1 D3.2 L6.2 Q2.4 SW.1
NetD4_1: D4.1 R67.1 | length 51.1
  Top Layer w8: R67.1@3275,1611.38 3325.91,1611.38 D4.1@3326.04,1611.24
NetD5_1: D5.1 R66.1 | length 52.9
  Top Layer w8: R66.1@3275,1731.38 3325.91,1731.38 D5.1@3327.28,1730
NetD6_1: D6.1 R68.1 | length 52.9
  Top Layer w8: R68.1@3275,1491.38 3276.38,1490 D6.1@3327.28,1490
NetD7_1: R107.2 VDD.1 | length 49.1
  Top Layer w8: R107.2@1123.62,600 VDD.1@1123.62,649.09
NetD8_1: D8.1 R108.2 | length 80
  Top Layer w8: R108.2@1691.38,2515 1691.38,2488.62 1710,2470 D8.1@1737.28,2470
NetJ1_1: J1.1 R12.2 | length 635.1
  Top Layer w30: R12.2@575,1336.5 v1(575,1390)
  Bottom Layer w8: J1.1@285.43,1764.37 285.43,1763.57 326.96,1722.04 326.96,1489.04 351,1465 500,1465 v1(575,1390)
NetJ1_3: J1.3 R8.1 | length 573.1
  Top Layer w30: R8.1@500,1336.5 v1(500,1390)
  Bottom Layer w8: J1.3@206.69,1685.63 206.69,1508.31 270,1445 445,1445 v1(500,1390)
NetJ2_1: J2.1 U2.13 | length 354.1
  Top Layer w8: 485,2520 525,2520 533.35,2528.35 U2.13@593.7,2528.35
  Top Layer w30: J2.1@270,2455 335,2520 485,2520
NetJ2_2: J2.2 U2.14 | length 408.1
  Top Layer w8: 485,2475 515,2475 548.67,2508.67 U2.14@593.7,2508.67
  Top Layer w30: J2.2@270,2305 440,2475 485,2475
NetJ7_1: J7.1 U8.13 | length 330.8
  Top Layer w8: U8.13@3346.16,2328.27 3488.27,2328.27 3490,2330
  Top Layer w30: 3490,2330 3655,2330 J7.1@3670,2315
NetJ7_2: J7.2 U8.14 | length 365.2
  Top Layer w8: U8.14@3346.16,2347.96 3417.96,2347.96 3435,2365
  Top Layer w30: 3440,2370 3535,2465 J7.2@3670,2465
NetJ8_1: J8.1 R76.1 R79.1 RT1.2 | length 289.4
  Top Layer w20: R76.1@3595,401.38 3668.62,401.38 RT1.2@3670,400 RT1.2@3678.5,391.5 ; R79.1@3678.5,315 RT1.2@3678.5,391.5 ; J8.1@3695,510 3678.5,493.5 RT1.2@3678.5,391.5
NetJ10_5: J10.5 R80.1 | length 88.5
  Top Layer w8: R80.1@3776.5,1860 J10.5@3865,1860
NetL2_1: L2.1 U2.7 U2.8 | length 58.5
  Top Layer w8: U2.8@668.5,2603.16 668.5,2618.31 cw(c678.34,2616.79) 688.19,2618.31 U2.7@688.18,2603.16
NetL7_1: L7.1 U8.7 U8.8 | length 58.5
  Top Layer w8: U8.7@3251.68,2253.47 3251.68,2238.32 ccw(c3261.52,2239.84) 3271.36,2238.32 U8.8@3271.36,2253.47
NetLOCK_1: LOCK.1 R53.2 U7.27 | length 254.5
  Top Layer w8: LOCK.1@2705.15,1360.15 2793.62,1448.62 R53.2@2815,1448.62 2815,1455 2838.53,1478.53 U7.27@2838.53,1546.83
NetMCLK_1: MCLK.1 U3.60 | length 429.4
  Top Layer w8: MCLK.1@880,1250 MCLK.1@879.75,1250.25 879.75,1343.52 925,1388.77 925,1561 979.22,1615.22 U3.60@1002.06,1615.22
NetQ1_1: Q1.1 Q1.2 Q1.3 R29.1 R31.2
NetQ1_4: Q1.4 R31.1 U9.32 | length 2246.3
  Top Layer w15: Q1.4@1480,664.57 1480,606.5 R31.1@1486.5,600
  Top Layer w20: R31.1@1486.5,600 1535,600 1610,525 1610,280 1695,195 2845,195 3189.45,539.45 U9.32@3211.57,539.45
NetQ2_1: Q2.1 R55.1 | length 212.5
  Top Layer w30: Q2.1@2758.86,390.24 2773.74,390.24 R55.1@2913.5,530
NetQ2_3: Q2.3 R52.2 R57.2
NetR3_2: R3.2 R4.1 U1.6 | length 207.6
  Top Layer w8: R3.2@366.5,845 R4.1@366.5,790 435,790 474.63,750.37 U1.6@474.63,722.29
NetR6_2: R6.2 R7.1 R13.2 | length 121.1
  Top Layer w8: R6.2@518.62,2080 R7.1@518.62,2025 568.5,2025 R13.2@580,2013.5
NetR9_2: R9.2 U2.15 | length 152.5
  Top Layer w8: R9.2@520,2381.5 520,2440 568.98,2488.98 U2.15@593.7,2488.98
NetR11_2: R11.2 U1.2 | length 199
  Top Layer w8: U1.2@533.69,883.71 533.69,933.69 565,965 565,1053.5 R11.2@553.5,1065
NetR21_1: R21.1 R22.2 U2.3 | length 137.4
  Top Layer w8: U2.3@743.3,2528.35 762.35,2528.35 800,2566 R21.1@803.88,2566 828.5,2541.37 R22.2@828.5,2515
NetR29_2: R29.2 R112.1 | length 398.7
  Top Layer w30: R112.1@1237.5,631 1275,593.5 1275,425 1380.79,319.21 R29.2@1380.79,291.65
NetR29_3: R29.3 U9.5 | length 2443.1
  Top Layer w20: R29.3@1479.21,498.35 1531.65,498.35 1575,455 1575,255 1665,165 3315,165 3375,225 3375,410 3391.69,426.69 U9.5@3391.69,485.31
NetR29_4: R29.4 U9.6 | length 2322.4
  Top Layer w20: R29.4@1479.21,291.65 1479.21,265.79 1610,135 3334.5,135 3410,210.5 3410,400 3423.19,413.19 U9.6@3423.19,485.31
NetR32_1: R32.1 R35.2 U3.15 | length 286.9
  Top Layer w8: U3.15@1309.15,1583.72 1309.15,1570.85 1365,1515 R35.2@1560,1515
NetR44_2: R44.2 U7.16 | length 148.2
  Top Layer w8: R44.2@2556.5,1675 2590,1675 2613.84,1651.16 U7.16@2694.83,1651.16
NetR45_1: R45.1 U7.18 | length 146.9
  Top Layer w8: R45.1@2548.62,1610 2550.41,1611.79 U7.18@2694.83,1611.79
NetR46_1: R46.1 U7.19 | length 157.4
  Top Layer w8: R46.1@2548.62,1565 2648,1565 2675.1,1592.1 U7.19@2694.83,1592.1
NetR55_2: R55.2 U9.30 | length 265.1
  Top Layer w8: R55.2@2976.5,530 3011.5,565 3120,565 3157.44,602.44 U9.30@3211.57,602.44
NetR58_1: R58.1 U7.29 | length 159.9
  Top Layer w8: U7.29@2877.9,1546.83 2877.9,1497.1 2907,1468 2938.5,1468 R58.1@2965,1441.5
NetR59_1: R59.1 U7.33 | length 92.6
  Top Layer w8: U7.33@2923.17,1611.79 2956.72,1611.79 R59.1@2998.5,1570
NetR61_2: R61.2 R62.1 U8.3 | length 126.8
  Top Layer w8: R62.1@3118.62,2270 3118.62,2312.13 R61.2@3126.5,2320 3134.77,2328.27 U8.3@3196.56,2328.27
NetR69_2: R69.2 R71.1 R72.2 | length 145.3
  Top Layer w8: R69.2@3305,2861.5 3358.5,2861.5 3371.38,2848.62 R71.1@3371.38,2825 R72.2@3371.38,2775
NetR74_2: R74.2 U8.15 | length 152.8
  Top Layer w8: U8.15@3346.16,2367.64 3387.64,2367.64 3425,2405 R74.2@3425,2463.5
NetR76_2: R76.2 U9.8 | length 124
  Top Layer w20: U9.8@3486.18,485.31 3558.31,485.31 R76.2@3595,448.62
NetR83_1: R83.1 U3.22 | length 248.2
  Top Layer w8: U3.22@1340.65,1733.33 1391.67,1733.33 1415,1710 v1(1475,1710)
  Bottom Layer w8: v1(1475,1710) 1481.79,1703.21 R83.1@1576.38,1703.21
NetR84_1: R84.1 U3.21 | length 256.6
  Top Layer w8: U3.21@1340.65,1713.64 1386.36,1713.64 1435,1665 v1(1475,1665)
  Bottom Layer w8: v1(1475,1665) 1574.59,1665 R84.1@1576.38,1663.21
NetR85_1: R85.1 U3.20 | length 265
  Top Layer w8: U3.20@1340.65,1693.96 1381.04,1693.96 1450,1625 v1(1505,1625)
  Bottom Layer w8: v1(1505,1625) 1574.59,1625 R85.1@1576.38,1623.21
NetR86_1: R86.1 U3.19 | length 287.2
  Top Layer w8: U3.19@1340.65,1674.27 1375.73,1674.27 1450,1600 1470,1600 v1(1505,1565)
  Bottom Layer w8: v1(1505,1565) 1530,1565 1545,1580 R86.1@1576.38,1580
NetR87_1: R87.1 U3.18 | length 297
  Top Layer w8: U3.18@1340.65,1654.59 1370.41,1654.59 v1(1460,1565)
  Bottom Layer w8: v1(1460,1565) 1460,1545 1470,1535 R87.1@1576.38,1535
NetR88_1: R88.1 U3.17 | length 322.1
  Top Layer w8: U3.17@1340.65,1634.9 1365.1,1634.9 1415,1585 v1(1415,1565)
  Bottom Layer w8: v1(1415,1565) 1415,1540 1440,1515 1526.3,1515 1551.3,1490 R88.1@1576.38,1490
NetR89_1: R89.1 U3.28 | length 226.6
  Top Layer w8: U3.28@1340.65,1851.44 1381.44,1851.44 v1(1480,1950)
  Bottom Layer w8: v1(1480,1950) R89.1@1526.38,1950
NetR90_1: R90.1 U3.27 | length 216.1
  Top Layer w8: U3.27@1340.65,1831.75 1391.75,1831.75 1465,1905 v1(1480,1905)
  Bottom Layer w8: v1(1480,1905) R90.1@1526.38,1905
NetR91_1: R91.1 U3.26 | length 204.4
  Top Layer w8: U3.26@1340.65,1812.07 1402.07,1812.07 1452.07,1862.07 v1@1477.93,1862.07
  Bottom Layer w8: v1(1480,1860) R91.1@1526.38,1860
NetR92_1: R92.1 U3.25 | length 195.1
  Top Layer w8: U3.25@1340.65,1792.38 1412.38,1792.38 1435,1815 v1(1480,1815)
  Bottom Layer w8: v1(1480,1815) R92.1@1526.38,1815
NetR93_1: R93.1 U3.23 | length 203.5
  Top Layer w8: U3.23@1340.65,1753.01 1401.99,1753.01 1415,1740 v1(1435,1740)
  Bottom Layer w8: v1(1435,1740) 1465,1740 1495,1770 R93.1@1526.38,1770
NetR94_1: R94.1 U3.33 | length 275.1
  Top Layer w8: U3.33@1269.78,1922.3 1269.78,1979.78 1290,2000 1335,2000 v1(1405,2070)
  Bottom Layer w8: v1(1405,2070) R94.1@1405,2115
NetR95_1: R95.1 U3.14 | length 100.3
  Top Layer w8: U3.14@1289.47,1583.72 1289.47,1545.53 v1(1300,1535)
  Bottom Layer w8: v1(1300,1535) 1300,1529.57 R95.1@1329.57,1500
NetR96_1: R96.1 U3.12 | length 206.5
  Top Layer w8: U3.12@1250.1,1583.72 1250.1,1464.9 v1(1265,1450)
  Bottom Layer w8: v1(1265,1450) 1324.57,1450 R96.1@1329.57,1455
NetR97_1: R97.1 U3.11 | length 259.7
  Top Layer w8: U3.11@1230.41,1583.72 1230.41,1439.59 v1(1265,1405)
  Bottom Layer w8: v1(1265,1405) 1324.57,1405 R97.1@1329.57,1410
NetR98_1: R98.1 U3.10 | length 320.4
  Top Layer w8: U3.10@1210.72,1583.72 1210.72,1394.28 v1(1235,1370)
  Bottom Layer w8: v1(1235,1370) 1240,1365 R98.1@1329.57,1365
NetR99_1: R99.1 U3.9 | length 385.3
  Top Layer w8: U3.9@1191.04,1583.72 1191.04,1348.96 v1(1205,1335)
  Bottom Layer w8: v1(1205,1335) 1220,1320 R99.1@1329.57,1320
NetR100_1: R100.1 U3.34 | length 255.8
  Top Layer w8: U3.34@1250.1,1922.3 1250.1,1990.1 1280,2020 1310,2020 v1(1360,2070)
  Bottom Layer w8: v1(1360,2070) R100.1@1360,2115
NetR101_1: R101.1 U3.35 | length 236.5
  Top Layer w8: U3.35@1230.41,1922.3 1230.41,2000.41 1270,2040 1285,2040 v1(1315,2070)
  Bottom Layer w8: v1(1315,2070) R101.1@1315,2115
NetR102_1: R102.1 U3.36 | length 217.2
  Top Layer w8: U3.36@1210.72,1922.3 1210.72,2010.72 v1(1270,2070)
  Bottom Layer w8: v1(1270,2070) R102.1@1270,2115
NetR103_1: R103.1 U3.37 | length 206.8
  Top Layer w8: U3.37@1191.04,1922.3 1191.04,2016.04 1225,2050 v1(1225,2070)
  Bottom Layer w8: v1(1225,2070) R103.1@1225,2115
NetR104_1: R104.1 U3.39 | length 215.5
  Top Layer w8: v1(1100,2070) 1151.67,2018.33 U3.39@1151.67,1922.3
  Bottom Layer w8: v1(1100,2070) R104.1@1100,2116.38
NetR105_1: R105.1 U3.40 | length 226
  Top Layer w8: v1(1055,2070) 1131.98,1993.02 U3.40@1131.98,1922.3
  Bottom Layer w8: v1(1055,2070) R105.1@1055,2116.38
NetR106_1: R106.1 U3.41 | length 236.4
  Top Layer w8: v1(1010,2070) 1112.3,1967.7 U3.41@1112.3,1922.3
  Bottom Layer w8: v1(1010,2070) R106.1@1010,2116.38
NLP8860_FAULT: R81.2 U7.7 U9.11 | length 3468.8
  Top Layer w8: U7.7@2779.47,1775.17 2779.47,1824.47 2800,1845 v1(2800,1885) ; U9.11@3540.31,602.44 3627.44,602.44 3655,630 3655,750 3680,775 R81.2@3713.5,775 3730,791.5 v1(3730,840)
  Bottom Layer w8: v1(2800,1885) 2800,1845 2787.28,1832.28 2670.47,1832.28 2605,1766.81 2605,1580 2510,1485 2420,1485 2215,1280 2215,1225.29 2255.29,1185 3080,1185 3103,1162 3103,837 3160,780 3525,780 3535,770 3690,770 3730,810 v1(3730,840)
NSS: U7.12 U9.17 | length 2333.5
  Top Layer w8: v1(2655,1725) 2659.9,1729.9 U7.12@2694.83,1729.9 ; U9.17@3486.18,814.06 3486.18,836.18 v1(3530,880)
  Bottom Layer w8: v1(2655,1725) 2655,1580 2515,1440 2427.63,1440 2365,1377.37 2365,1245 2389.39,1220.61 3099.39,1220.61 3135,1185 3135,860 3175,820 3470,820 v1(3530,880)
OEN: R42.2 R45.2 U3.31 | length 3040.6
  Top Layer w8: U3.31@1309.15,1922.3 1309.15,1946.15 1313,1950 v1(1345,1950) ; R42.2@2410,1560.43 2410,1595 2425,1610 v1(2455,1610) R45.2@2501.38,1610
  Inner Routing w8: v1(1345,1950) 1280.57,1885.57 875.57,1885.57 824,1834 824,1691 838.79,1676.21 898.79,1676.21 965,1610 965,1440 1013.79,1391.21 1098.79,1391.21 1250,1240 2115,1240 2135,1260 2135,1370 2375,1610 v1(2455,1610)
OSSSEL: R46.2 U3.46 | length 2593.4
  Top Layer w8: v1(960,1920) 989.19,1890.81 U3.46@1002.06,1890.81 ; v1(2455,1565) R46.2@2501.38,1565
  Inner Routing w8: v1(960,1920) 883.13,1920 805,1841.87 805,1680 830,1655 890,1655 943.79,1601.21 943.79,1431.21 1005,1370 1090,1370 1238.86,1221.14 2171.14,1221.14 2215,1265 2215,1370 2410,1565 v1(2455,1565)
PASS: PASS.1 R56.2 R58.2 R68.2 U3.42 | length 4796.6
  Top Layer w8: v1(1010,2025) 1015,2025 1092.61,1947.39 U3.42@1092.61,1922.3 ; R58.2@2965,1378.5 2965,1326.38 R56.2@2963.62,1325 3035,1325 PASS.1@3070,1360 3248.62,1538.62 R68.2@3275,1538.62
  Inner Routing w8: v1(1010,2025) 988.54,2025 978.7,2034.84 978.7,2071.3 920,2130 725,2130 635,2040 635,1890 685,1840 685,1030 845,870 1120,870 1330,1080 2859.49,1080 3040,1260.51 3040,1330 PASS.1@3070,1360
PDB: R19.2 U3.59 U7.25 | length 2965.1
  Top Layer w8: v1(760,1220) 760,1268.62 R19.2@758.62,1270 758.62,1318.62 775,1335 830,1335 905,1410 905,1565 974.9,1634.9 U3.59@1002.06,1634.9 ; v1(2570,1355) 2570,1380 2635,1445 2740,1445 2799.16,1504.16 U7.25@2799.16,1546.83
  Inner Routing w8: v1(760,1220) 890,1090 1085,1090 1135,1140 2465,1140 2587.27,1262.27 2587.27,1337.73 v1(2570,1355)
PG_VDD: R5.2 U1.3 | length 137.2
  Top Layer w8: R5.2@463.5,1000 478,985.5 478,972 514,936 U1.3@514,883.71
RED0: J11.3 R106.2 | length 1158.9
  Bottom Layer w8: R106.2@1010,2163.62 1010,2210 1140,2340 1638.44,2340 1748.57,2229.87 1765,2229.87 1765.25,2230.12 1835.12,2230.12 1905.2,2300.2 J11.3@1993.9,2300.2
RED1: J11.5 R105.2 | length 1097.1
  Bottom Layer w8: R105.2@1055,2163.62 1055,2210 1165,2320 1636.52,2320 1742.15,2214.37 1849.37,2214.37 1903.71,2268.71 J11.5@1993.9,2268.71
RED2: J11.7 R104.2 | length 1035.5
  Bottom Layer w7: 1857.91,2198.62 1858.62,2198.62 1897.21,2237.21 J11.7@1993.9,2237.21
  Bottom Layer w8: R104.2@1100,2163.62 1100,2210 1190,2300 1634.6,2300 1735.98,2198.62 1857.91,2198.62
RED3: J11.9 R103.2 | length 883.6
  Bottom Layer w8: R103.2@1225,2162.24 1225,2190 1315,2280 1632.68,2280 1729.81,2182.87 1864.09,2182.87 1886.93,2205.72 J11.9@1993.9,2205.72
RED4: J11.13 R102.2 | length 829.2
  Bottom Layer w8: R102.2@1270,2162.24 1270,2190 1340,2260 1630.76,2260 1723.63,2167.13 1862.87,2167.13 1887.28,2142.72 J11.13@1993.9,2142.72
RED5: J11.15 R101.2 | length 780.7
  Bottom Layer w8: R101.2@1315,2162.24 1315,2190 1365,2240 1628.84,2240 1717.46,2151.38 1853.82,2151.38 1893.97,2111.23 J11.15@1993.9,2111.23
RED6: J11.17 R100.2 | length 732.2
  Bottom Layer w8: R100.2@1360,2162.24 1360,2190 1390,2220 1626.92,2220 1711.29,2135.63 1847.65,2135.63 1903.55,2079.73 J11.17@1993.9,2079.73
RED7: J11.19 R94.2 | length 683.7
  Bottom Layer w8: R94.2@1405,2162.24 1405,2190 1415,2200 1625,2200 1705.12,2119.88 1841.48,2119.88 1913.12,2048.24 J11.19@1993.9,2048.24
RIN_N: J1.4 L3.1 | length 531
  Top Layer w5: J1.4@285.43,1685.63 cw(c285.43,1725.06) 246,1725.06 246,1810.26 cw(c253.24,1810.26) 253.24,1817.5 268.12,1817.5 591,1817.5 cw(c591,1804.22) 600.39,1813.61 603.07,1810.93 ccw(c621.54,1829.4) L3.1@621.54,1803.28
RIN_P: J1.2 L3.4 | length 442.9
  Top Layer w5: J1.2@227,1768.34 228,1768.34 228.04,1768.38 ccw(c206.42,1790) 237,1790 237,1811 cw(c253,1811) 253,1827 593.41,1827 ccw(c593.41,1840.49) 602.95,1830.95 603.07,1831.07 cw(c621.54,1812.6) L3.4@621.54,1838.72
"RX (TX)": J10.6 U7.24 | length 1933.7
  Top Layer w8: v1(2520,1355) 2520,1360 2625,1465 2735,1465 2779.47,1509.47 U7.24@2779.47,1546.83
  Bottom Layer w8: v1(2520,1355) 2527.63,1355 2611.63,1439 2741.63,1439 2933.63,1631 3166,1631 3204,1669 3204,1699 3272.37,1767.37 3530,1767.37 3567.63,1805 J10.6@3886,1805
SBWTCK: J10.4 U7.37 | length 1076.3
  Top Layer w8: U7.37@2923.17,1690.53 2975.53,1690.53 3024.75,1739.75 3120.25,1739.75 v1(3150,1710)
  Bottom Layer w8: v1(3150,1710) 3225,1785 3525,1785 3645,1905 J10.4@3886,1905
SCL: J5.1 J11.45 R48.1 U3.3 U6.4 U9.16 | length 5406.2
  Top Layer w8: v1(1020,1475) 1072.93,1527.93 U3.3@1072.93,1583.72 ; v1(1845,1580) 1845,1600 1883.79,1638.79 2078.79,1638.79 2115,1675 2115,2240 2143.71,2268.71 2518.71,2268.71 J5.1@2585,2335 2585,2240 2641.5,2183.5 2675,2183.5 2675,2150 2734.53,2090.47 U6.4@2804.8,2090.47 ; U9.16@3560,760 v1(3560,810)
  Inner Routing w8: v1(1020,1475) 1045,1500 1255,1500 1275,1480 1428.5,1480 1473.5,1435 1700,1435 v1(1845,1580) ; v1(3460,1950) 3515,1895 3515,960 3560,915 v1(3560,810)
  Bottom Layer w8: v1(1845,1580) 1845,1610 1873.79,1638.79 J11.45@1993.9,1638.79 ; J5.1@2585,2335 2650.75,2269.25 2804.25,2269.25 2860,2325 2935,2325 2955,2305 2955,2205 3070,2090 3320,2090 v1(3460,1950)
SCL_DRV2667: J5.2 R109.1 U4.7 U6.2 | length 1639.7
  Top Layer w8: U4.7@1850.2,2665.16 1950.16,2665.16 1975,2690 2200,2690 2225,2665 2225,2525 2265,2485 2535,2485 J5.2@2585,2435 2645,2435 2695,2385 2790,2385 2805,2370 2805,2215 2770,2180 2770,2145 2785.16,2129.84 U6.2@2804.8,2129.84 ; v1(2505,2535) R109.1@2505,2581.38
  Inner Routing w8: v1(2505,2535) 2505,2515 J5.2@2585,2435
SCL_DRV2667_1: R37.1 U4.2 U8.18 | length 2240.5
  Top Layer w8: R37.1@1678.34,2698.99 v1(1731.01,2698.99) 1745.16,2684.84 U4.2@1799.8,2684.84 ; v1(2875,2700) 2920,2700 3000,2620 3175,2620 3271.36,2523.64 U8.18@3271.36,2403.08
  Bottom Layer w8: v1(1731.01,2698.99) 1711.01,2698.99 1700,2710 1700,2835 1745,2880 1920,2880 1955,2845 1955,2705 1975,2685 2835,2685 2850,2700 v1(2875,2700)
SCL_DRV2667_2: R39.1 U2.18 U4.4 | length 1529.7
  Top Layer w8: U2.18@668.5,2453.55 668.5,2306.5 v1(685,2290) ; R39.1@1678.34,2605 v1(1730,2605) 1770.47,2645.47 U4.4@1799.8,2645.47
  Bottom Layer w8: v1(685,2290) 730,2290 785,2235 900,2235 1220,2555 1622.66,2555 1672.66,2605 v1(1730,2605)
SCL_UC: R47.1 SCL.1 U6.7 U7.11 | length 1168
  Top Layer w8: v1(2530,1950) 2560,1920 2613.75,1920 2650,1883.75 R47.1@2650,1823.62 2671.88,1823.62 2680,1815.5 2680,1783 2694.83,1768.17 U7.11@2694.83,1749.58 ; U6.7@2855.2,2110.16 2899.84,2110.16 v1(2920,2090)
  Inner Routing w8: SCL.1@2350,2180 2530,2000 v1(2530,1950)
  Bottom Layer w8: v1(2530,1950) 2590,2010 2890,2010 2920,2040 v1(2920,2090)
SDA: J6.1 J11.43 R51.1 U3.2 U6.3 U9.15 | length 5413.5
  Top Layer w8: v1(1020,1525) 1053.24,1558.24 U3.2@1053.24,1583.72 ; v1(1805,1610) 1850,1655 2055,1655 2095,1695 2095,2248.28 2135.42,2288.71 2465,2288.71 2495,2318.71 2495,2360 2520,2385 2640,2385 2690,2335 J6.1@2750,2335 2775,2310 2775,2228.5 2730,2183.5 2730,2150 2769.84,2110.16 U6.3@2804.8,2110.16 ; U9.15@3540.31,728.43 3588.43,728.43 3595,735 v1(3595,840)
  Inner Routing w8: v1(1020,1525) 1260,1525 1285,1500 1440,1500 1485,1455 1650,1455 v1(1805,1610) ; v1(3495,1985) 3535,1945 3535,967.63 3595,907.63 v1(3595,840)
  Bottom Layer w8: v1(1805,1610) 1865.28,1670.28 J11.43@1993.9,1670.28 ; J6.1@2750,2335 2760,2345 2950,2345 2975,2320 2975,2215 3080,2110 3370,2110 v1(3495,1985)
SDA_DRV2667: J6.2 R110.1 U4.8 U6.1 | length 1744
  Top Layer w8: U4.8@1850.2,2684.84 1939.84,2684.84 1965,2710 2210,2710 2245,2675 2245,2535 2275.25,2504.75 2610.25,2504.75 2680,2435 J6.2@2750,2435 2800,2435 2825,2410 2825,2205 2804.8,2184.8 U6.1@2804.8,2149.53 ; v1(2555,2536.99) R110.1@2555,2581.38 R110.1@2555,2583.37
  Inner Routing w8: v1(2555,2536.99) 2648.01,2536.99 J6.2@2750,2435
